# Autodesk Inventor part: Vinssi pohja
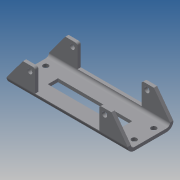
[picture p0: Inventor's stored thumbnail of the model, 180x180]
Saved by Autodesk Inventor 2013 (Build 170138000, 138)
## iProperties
Created: 2013-08
Part Number: Vinssi pohja
Material: Generic
Document SubType Name: Sheet Metal
Designer: Reko Tuppurainen
Density: 1 g/cm^3
Sheet Metal Rule: Default_mm
Author: Reko Tuppurainen
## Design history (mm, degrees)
node "Face1"
  sketch "Sketch1"
    geometry: L1 (-148.5, 56)-(148.5, 56); L2 (148.5, 56)-(148.5, -56); L3 (148.5, -56)-(-148.5, -56); L4 (-148.5, -56)-(-148.5, 56); 2 further points
    constraints: 8 end point, 2 parallel, 1 coincident, 1 horizontal, 1 perpendicular
    dimensions: "d0" = 297 distance of L2.end L3.end; "d1" = 112 distance of L1.end L2.end
node "Flange1"
sketch "Sketch3"
  geometry: L1 (-91, -12.5)-(91, -12.5); L2 (91, -12.5)-(91, 12.5); L3 (91, 12.5)-(-91, 12.5); L4 (-91, 12.5)-(-91, -12.5); L5 (-91, -12.5)-(91, 12.5); 3 further points
  constraints: 10 end point, 2 coincident, 2 parallel, 1 horizontal, 1 midpoint, 1 perpendicular
  dimensions: "d15" = 182 distance of L3.end L2.end; "d16" = 25 distance of L2.end L1.end
cut "Cut1" sketch "Sketch3" dims "d17" = 8 (= Thickness), "d18" = 0
sketch "Sketch4"
  geometry: L1 (-148.5, -40)-(148.5, -40) reference; L2 (148.5, 40)-(148.5, -40) reference; L3 (148.5, 40)-(-148.5, 40) reference; L4 (-148.5, -40)-(-148.5, 40) reference; C1 r 6.5 at (-132.5, 24); C2 r 6.5 at (-132.5, -24); C3 r 6.5 at (132.5, 24); C4 r 6.5 at (132.5, -24); 1 further point
  constraints: 4 centre point
  dimensions: "d19" = 13 diameter of C1; "d20" = 13 diameter of C2; "d21" = 13 diameter of C3; "d22" = 13 diameter of C4; "d23" = 16 distance from line of C1.centre L3; "d24" = 16 distance from line of L4 C1.centre; "d25" = 16 distance from line of L4 C2.centre; "d26" = 16 distance from line of L1 C2.centre; "d27" = 16 distance from line of L1 C4.centre; "d28" = 16 distance from line of L2 C4.centre; "d29" = 16 distance from line of L2 C3.centre; "d30" = 16 distance from line of L3 C3.centre
cut "Cut2" sketch "Sketch4" dims "d31" = 8 (= Thickness), "d32" = 0
sketch "Sketch5"
  geometry: L1 (297, 54)-(0, 54) reference; L2 (0, 0)-(0, 54) reference; L3 (297, 0)-(0, 0) reference; L4 (297, 54)-(297, 0) reference; L5 (70, 0)-(70, 54); L6 (227, 0)-(227, 54); 1 further point
  constraints: 4 end point, 4 point on line, 2 perpendicular
  dimensions: "d33" = 70 distance between parallel lines of L2 L5; "d34" = 70 distance between parallel lines of L4 L6
cut "Cut3" sketch "Sketch5" dims "d35" = 8 (= Thickness), "d36" = 0
sketch "Sketch6"
  geometry: L1 (0, 0)-(0, 54) reference; L2 (70, 0)-(0, 0) reference; L3 (0, 0)-(40, 0); L4 (40, 0)-(0, 54); 1 further point
  constraints: 4 end point, 1 point on line
  dimensions: "d37" = 40 distance of L1.start L3.end
cut "Cut4" sketch "Sketch6" dims "d38" = 8 (= Thickness), "d39" = 0
sketch "Sketch7"
  geometry: L1 (0, 0)-(-70, 0) reference; L2 (0, 54)-(0, 0) reference; L3 (0, 0)-(-40, 0); L4 (-40, 0)-(0, 54); 1 further point
  constraints: 4 end point, 1 point on line
  dimensions: "d40" = 40 distance of L1.start L3.end
cut "Cut5" sketch "Sketch7" dims "d41" = 8 (= Thickness), "d42" = 0
feature "Corner Round1" dims "d43" = 6
sketch "Sketch8"
  geometry: L1 (70, -48)-(70, 0) reference; L2 (64, -54)-(40, -54) reference; C1 r 6 at (57, -41); 1 further point
  constraints: 1 centre point
  dimensions: "d44" = 12 diameter of C1; "d45" = 13 distance from line of C1.centre L2; "d46" = 13 distance from line of L1 C1.centre
cut "Cut6" sketch "Sketch8" dims "d47" = 8 (= Thickness), "d48" = 0
sketch "Sketch9"
  geometry: L1 (30, -54)-(6, -54) reference; L2 (0, 0)-(0, -48) reference; C1 r 6.5 at (13, -41); 1 further point
  constraints: 1 centre point
  dimensions: "d49" = 13 diameter of C1; "d50" = 13 distance from line of L2 C1.centre; "d51" = 13 distance from line of C1.centre L1
cut "Cut7" sketch "Sketch9" dims "d52" = 8 (= Thickness), "d53" = 0
body "Solid1"
face "Plate1" dims "Thickness" = 8 (derived)
sketch "Sketch2"
  geometry: L1 through (-148.5, 0) direction (1, 0); L2 through (0, 35) direction (0, 1); L3 (0, 70)-(-297, 70); L4 (-297, 70)-(-297, 0)
  constraints: 6 end point, 1 horizontal, 1 perpendicular, 1 vertical
face "Plate2" dims "d3" = 8 (= BendReliefWidth), "d4" = 4 (= BendReliefDepth), "d5" = 16 (= MinimumRemnant), "d6" = 8 (= BendRadius), "d7" = 70, "d8" = 90 deg, "d9" = 8 (= BendRadius), "d10" = 32 (= CornerReliefSize), "d11" = 8 (= GapSize), "d12" = 8 (= JacobiRadiusSize), "SeamGap" = 0.01, "Thickness" = 8 (derived)
bend "Bend1" dims "d3" = 8 (= BendReliefWidth), "d4" = 4 (= BendReliefDepth), "d5" = 16 (= MinimumRemnant), "d6" = 8 (= BendRadius), "d7" = 70, "d8" = 90 deg, "d9" = 8 (= BendRadius), "SeamGap" = 0.01, "Thickness" = 8 (derived)
feature "Corner1" dims "d7" = 70, "d8" = 90 deg, "d10" = 32 (= CornerReliefSize), "d11" = 8 (= GapSize), "d12" = 8 (= JacobiRadiusSize)
other parameters: "BendRadius" = 8 (= Thickness), "BendReliefWidth" = 8 (= Thickness), "BendReliefDepth" = 4 (= 0.5 x Thickness), "CornerReliefSize" = 32 (= 4 x Thickness), "MinimumRemnant" = 16 (= 2 x Thickness), "TransitionRadius" = 8 (= BendRadius), "JacobiRadiusSize" = 8 (= BendRadius), "GapSize" = 8 (= Thickness), "d2" = 8 (= BendRadius)
